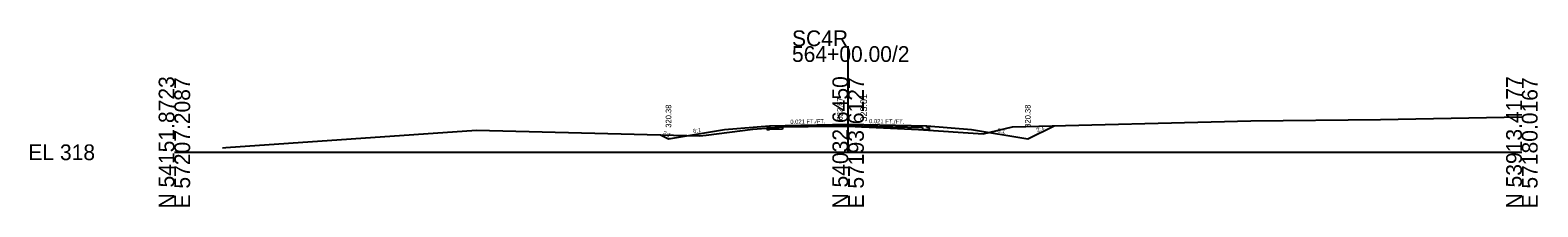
# Model space of a CAD drawing. Extents: x 9740 to 17409, y 8856 to 28416.
# Drawn here: x 12740.2 to 13008.7, y 24861.7 to 24893.1 of the extents above; entities that cross this region are included whole.
import ezdxf

# ---------------------------------------------------------------- set-up
doc = ezdxf.new("R2010")
doc.units = 0
for name, color, linetype in [('Level 10', 7, 'Continuous'), ('Level 11', 7, 'Continuous'), ('Level 12', 7, 'Continuous'), ('Level 32', 7, 'Continuous'), ('Level 33', 7, 'Continuous'), ('Level 53', 7, 'Continuous'), ('Level 59', 7, 'Continuous'), ('Level 6', 7, 'Continuous'), ('Level 60', 7, 'Continuous'), ('Level 63', 7, 'Continuous'), ('Level 7', 7, 'Continuous')]:
    doc.layers.add(name, color=color, linetype=linetype)

msp = doc.modelspace()

# ---------------------------------------------------------------- linework, layer by layer
at = {"layer": 'Level 11'}
for p, q in [((12871.85, 24875.8), (12871.35, 24875.79)), ((12871.35, 24875.79), (12871.35, 24875.45)), ((12871.35, 24875.45), (12871.85, 24875.46)), ((12871.85, 24876.1), (12871.85, 24875.8)), ((12899.85, 24875.8), (12899.85, 24876.1)), ((12900.35, 24875.79), (12899.85, 24875.8)), ((12899.85, 24875.46), (12900.35, 24875.45)), ((12900.35, 24875.45), (12900.35, 24875.79))]:
    msp.add_line(p, q, dxfattribs=at)
at = {"layer": 'Level 12'}
for p, q in [((12874.15, 24875.5), (12871.85, 24875.46)), ((12874.15, 24875.9), (12874.15, 24875.5)), ((12899.09, 24875.38), (12899.09, 24875.47)), ((12899.09, 24875.47), (12899.85, 24875.46))]:
    msp.add_line(p, q, dxfattribs=at)
at = {"layer": 'Level 53'}
for p, q in [((12885.85, 24876.09), (12874.15, 24875.84)), ((12885.85, 24876.09), (12899.09, 24875.81)), ((12899.09, 24875.81), (12899.09, 24875.38))]:
    msp.add_line(p, q, dxfattribs=at)
at = {"layer": 'Level 59'}
for p, q in [((12871.85, 24876.1), (12885.85, 24876.39)), ((12885.85, 24876.39), (12899.85, 24876.1))]:
    msp.add_line(p, q, dxfattribs=at)
at = {"layer": 'Level 6'}
for p, q in [((12863.85, 24875.43), (12871.85, 24876.1)), ((12899.85, 24876.1), (12907.85, 24875.43))]:
    msp.add_line(p, q, dxfattribs=at)
at = {"layer": 'Level 60'}
for p, q in [((12915.12, 24875.93), (12957.59, 24876.95)), ((12957.59, 24876.95), (12980.68, 24877.21)), ((12980.68, 24877.21), (13005.85, 24877.67)), ((12775.01, 24872.21), (12819.68, 24875.29)), ((12819.68, 24875.29), (12859.45, 24874.29)), ((12859.45, 24874.29), (12860.58, 24874.43)), ((12860.58, 24874.43), (12868.85, 24875.49)), ((12868.85, 24875.49), (12872.05, 24875.74)), ((12872.05, 24875.74), (12874.34, 24875.92)), ((12874.34, 24875.92), (12883.14, 24876.02)), ((12883.14, 24876.02), (12885.85, 24876.05)), ((12885.85, 24876.05), (12898.38, 24875.43)), ((12898.38, 24875.43), (12909.89, 24874.67)), ((12909.89, 24874.67), (12915.12, 24875.93)), ((12774.43, 24872.19), (12775.01, 24872.21))]:
    msp.add_line(p, q, dxfattribs=at)
at = {"layer": 'Level 63'}
for p, q in [((12885.85, 24871.38), (12885.85, 24890.25)), ((12765.85, 24871.38), (12885.85, 24871.38)), ((12885.85, 24871.38), (13005.85, 24871.38))]:
    msp.add_line(p, q, dxfattribs=at)
at = {"layer": 'Level 7'}
for p, q in [((12852.45, 24874.47), (12853.85, 24873.76)), ((12853.85, 24873.76), (12863.85, 24875.43)), ((12907.85, 24875.43), (12917.85, 24873.76)), ((12917.85, 24873.76), (12922.55, 24876.11))]:
    msp.add_line(p, q, dxfattribs=at)

# ---------------------------------------------------------------- texts
at = {"layer": 'Level 10'}
msp.add_text('322.67', height=1, rotation=90, dxfattribs=at).set_placement((12884.85, 24877.05))
at = {"layer": 'Level 32'}
for s, rotation, p in [('0.021 FT./FT.', 1.1916, (12875.56, 24876.42)), ('0.021 FT./FT.', 358.8084, (12889.57, 24876.56)), ('2:1', 333.435, (12852.76, 24874.59)), ('6:1', 9.4623, (12858.29, 24874.76)), ('6:1', 350.5377, (12912.37, 24874.93)), ('2:1', 26.5651, (12919.58, 24874.91))]:
    msp.add_text(s, height=0.75, rotation=rotation, dxfattribs=at).set_placement(p)
at = {"layer": 'Level 33'}
for p in [(12854.35, 24875.76), (12918.35, 24875.76)]:
    msp.add_text('320.38', height=1, rotation=90, dxfattribs=at).set_placement(p)
at = {"layer": 'Level 59'}
msp.add_text(' 323.01', height=1.2, rotation=90, dxfattribs=at).set_placement((12889.22, 24876.39))
at = {"layer": 'Level 63'}
for s, p in [('SC4R', (12875.85, 24890.25)), ('564+00.00/2', (12875.85, 24887.45)), ('EL 318', (12739.85, 24869.98))]:
    msp.add_text(s, height=2.8, dxfattribs=at).set_placement(p)
for s, p in [('N 54151.8723', (12765.85, 24861.38)), ('E 57207.2087', (12768.65, 24861.38)), ('N 54032.6450', (12885.85, 24861.38)), ('E 57193.6127', (12888.65, 24861.38)), ('N 53913.4177', (13005.85, 24861.38)), ('E 57180.0167', (13008.65, 24861.38))]:
    msp.add_text(s, height=2.8, rotation=90, dxfattribs=at).set_placement(p)

doc.saveas('drawing.dxf')
